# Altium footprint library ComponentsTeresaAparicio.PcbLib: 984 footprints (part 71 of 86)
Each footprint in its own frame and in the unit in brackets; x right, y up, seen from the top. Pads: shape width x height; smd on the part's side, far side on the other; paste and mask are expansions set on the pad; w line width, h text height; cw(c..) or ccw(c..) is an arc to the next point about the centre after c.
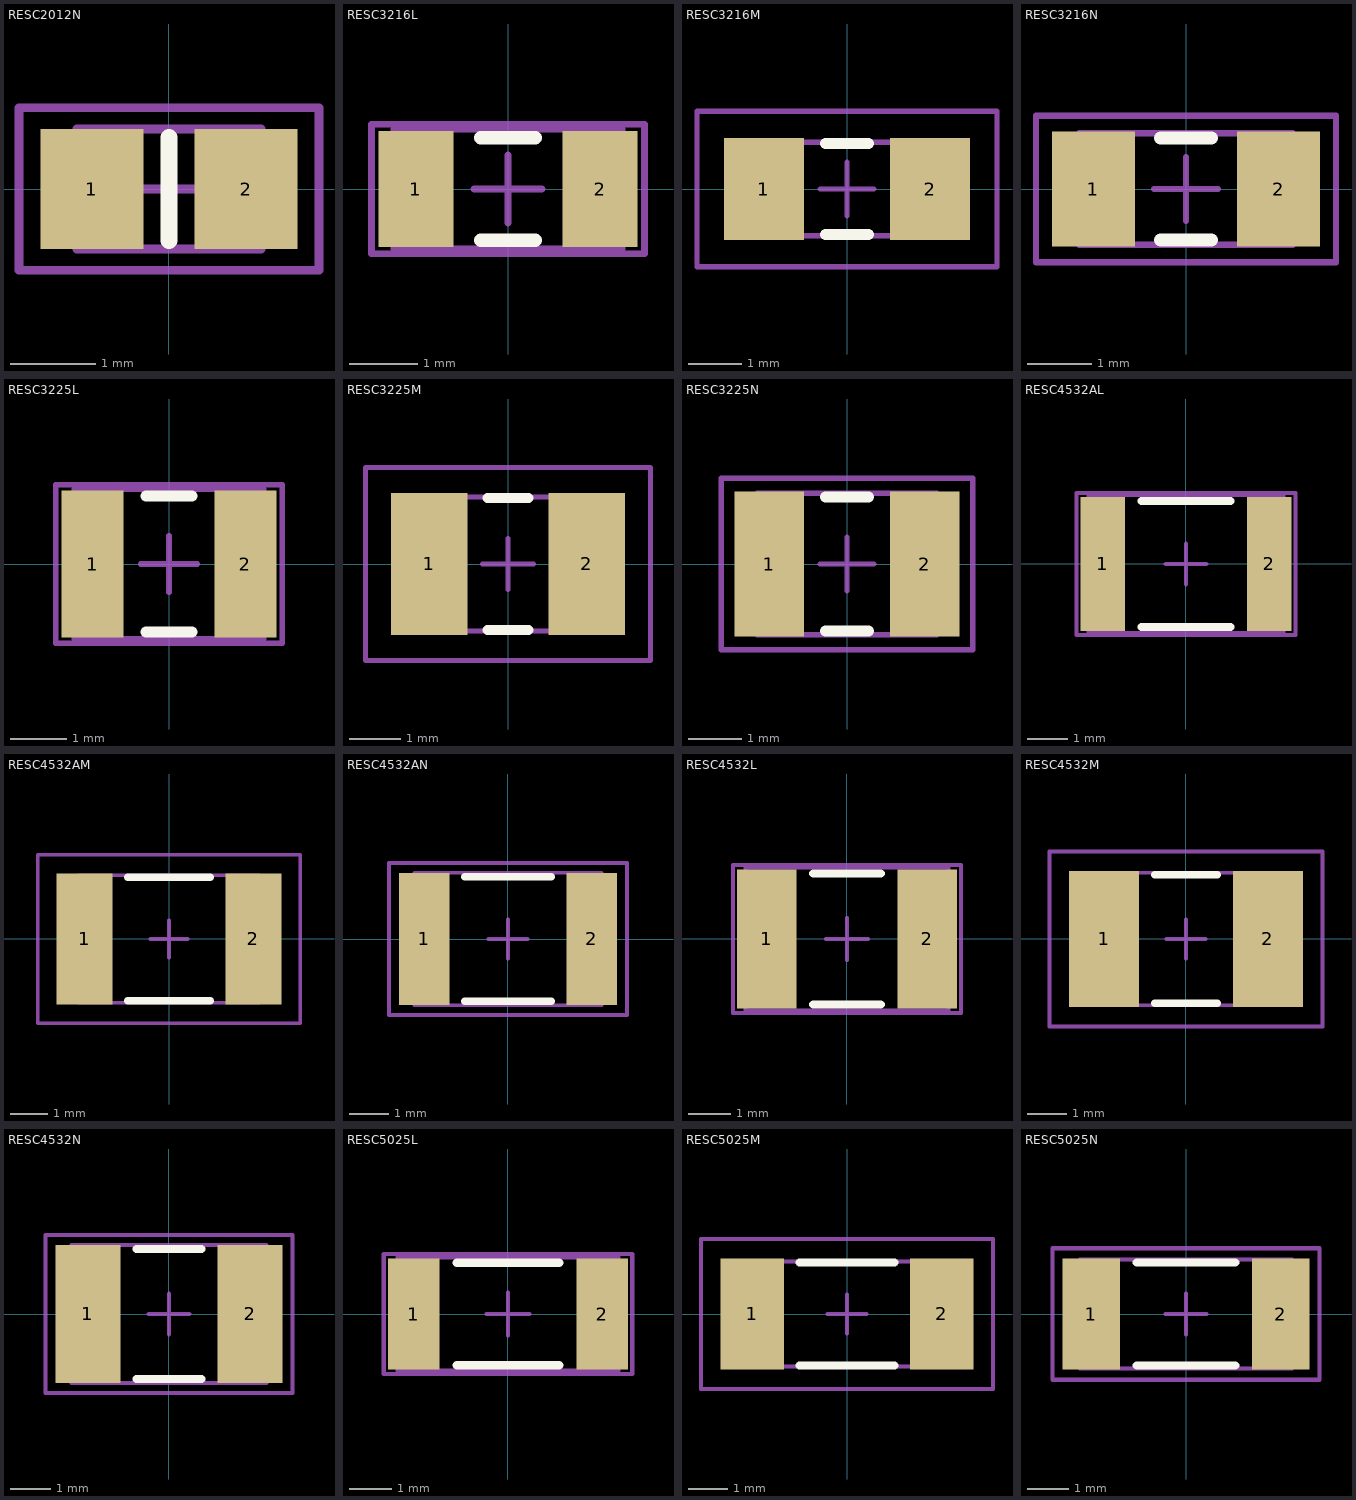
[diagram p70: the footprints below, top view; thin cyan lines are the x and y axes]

## RESC2012N [mm] "Chip Resistor, Body 2.0x1.3mm, IPC Medium Density"
height 0.65
pads (2):
  rect 1.2x1.4 smd: 1(-0.9,0) 2(0.9,0)
Top Overlay:
  lines w0.2: 0,-0.6 0,0.6
Mechanical 13:
  lines w0.1: -1.075,-0.7 1.075,-0.7 1.075,0.7 -1.075,0.7 -1.075,-0.7
Mechanical 15:
  lines w0.1: -0.5,0 0.5,0 ; 0,-0.5 0,0.5 ; -1.75,-0.95 1.75,-0.95 1.75,0.95 -1.75,0.95 -1.75,-0.95
3D body: height 0.65, standoff 0, extent -1.075,-0.7 1.075,0.7

## RESC3216L [mm] "Chip Resistor, Body 3.2x1.6mm, IPC High Density"
height 0.71
pads (2):
  rect 1.1x1.7 smd: 1(-1.35,0) 2(1.35,0)
Top Overlay:
  lines w0.2: -0.4,-0.75 0.4,-0.75 ; -0.4,0.75 0.4,0.75
Mechanical 13:
  lines w0.1: -1.675,-0.875 1.675,-0.875 1.675,0.875 -1.675,0.875 -1.675,-0.875
Mechanical 15:
  lines w0.1: -0.5,0 0.5,0 ; 0,-0.5 0,0.5 ; -2,-0.95 2,-0.95 2,0.95 -2,0.95 -2,-0.95
3D body: height 0.71, standoff 0, extent -1.675,-0.875 1.675,0.875

## RESC3216M [mm] "Chip Resistor, Body 3.2x1.6mm, IPC Low Density"
height 0.71
pads (2):
  rect 1.5x1.9 smd: 1(-1.55,0) 2(1.55,0)
Top Overlay:
  lines w0.2: -0.4,-0.85 0.4,-0.85 ; -0.4,0.85 0.4,0.85
Mechanical 13:
  lines w0.1: -1.675,-0.875 -1.675,0.875 1.675,0.875 1.675,-0.875 -1.675,-0.875
Mechanical 15:
  lines w0.1: -0.5,0 0.5,0 ; 0,-0.5 0,0.5 ; -2.8,-1.45 -2.8,1.45 2.8,1.45 2.8,-1.45 -2.8,-1.45
3D body: height 0.71, standoff 0, extent -1.675,-0.875 1.675,0.875

## RESC3216N [mm] "Chip Resistor, Body 3.2x1.6mm, IPC Medium Density"
height 0.71
pads (2):
  rect 1.3x1.8 smd: 1(-1.45,0) 2(1.45,0)
Top Overlay:
  lines w0.2: -0.4,-0.8 0.4,-0.8 ; -0.4,0.8 0.4,0.8
Mechanical 13:
  lines w0.1: -1.675,-0.875 -1.675,0.875 1.675,0.875 1.675,-0.875 -1.675,-0.875
Mechanical 15:
  lines w0.1: -0.5,0 0.5,0 ; 0,-0.5 0,0.5 ; -2.35,-1.15 -2.35,1.15 2.35,1.15 2.35,-1.15 -2.35,-1.15
3D body: height 0.71, standoff 0, extent -1.675,-0.875 1.675,0.875

## RESC3225L [mm] "Chip Resistor, Body 3.2x2.5mm, IPC High Density"
height 0.71
pads (2):
  rect 1.1x2.6 smd: 1(-1.35,0) 2(1.35,0)
Top Overlay:
  lines w0.2: -0.4,-1.2 0.4,-1.2 ; -0.4,1.2 0.4,1.2
Mechanical 13:
  lines w0.1: -1.675,-1.32 -1.675,1.32 1.675,1.32 1.675,-1.32 -1.675,-1.32
Mechanical 15:
  lines w0.1: -0.5,0 0.5,0 ; 0,-0.5 0,0.5 ; -2,-1.4 -2,1.4 2,1.4 2,-1.4 -2,-1.4
3D body: height 0.71, standoff 0, extent -1.675,-1.32 1.675,1.32

## RESC3225M [mm] "Chip Resistor, Body 3.2x2.5mm, IPC Low Density"
height 0.71
pads (2):
  rect 1.5x2.8 smd: 1(-1.55,0) 2(1.55,0)
Top Overlay:
  lines w0.2: -0.4,-1.3 0.4,-1.3 ; -0.4,1.3 0.4,1.3
Mechanical 13:
  lines w0.1: -1.675,-1.32 1.675,-1.32 1.675,1.32 -1.675,1.32 -1.675,-1.32
Mechanical 15:
  lines w0.1: -0.5,0 0.5,0 ; 0,-0.5 0,0.5 ; -2.8,-1.9 2.8,-1.9 2.8,1.9 -2.8,1.9 -2.8,-1.9
3D body: height 0.71, standoff 0, extent -1.675,-1.32 1.675,1.32

## RESC3225N [mm] "Chip Resistor, Body 3.2x2.5mm, IPC Medium Density"
height 0.71
pads (2):
  rect 1.3x2.7 smd: 1(-1.45,0) 2(1.45,0)
Top Overlay:
  lines w0.2: -0.4,-1.25 0.4,-1.25 ; -0.4,1.25 0.4,1.25
Mechanical 13:
  lines w0.1: -1.675,-1.32 1.675,-1.32 1.675,1.32 -1.675,1.32 -1.675,-1.32
Mechanical 15:
  lines w0.1: -0.5,0 0.5,0 ; 0,-0.5 0,0.5 ; -2.35,-1.6 2.35,-1.6 2.35,1.6 -2.35,1.6 -2.35,-1.6
3D body: height 0.71, standoff 0, extent -1.675,-1.32 1.675,1.32

## RESC4532AL [mm] "Chip Resistor, Body 4.5x3.2mm, IPC High Density"
height 0.7
pads (2):
  rect 1.1x3.3 smd: 1(-2.05,0) 2(2.05,0)
Top Overlay:
  lines w0.2: -1.1,-1.55 1.1,-1.55 ; -1.1,1.55 1.1,1.55
Mechanical 13:
  lines w0.1: -2.4,-1.7 2.4,-1.7 2.4,1.7 -2.4,1.7 -2.4,-1.7
Mechanical 15:
  lines w0.1: -0.5,0 0.5,0 ; 0,-0.5 0,0.5 ; -2.7,-1.75 2.7,-1.75 2.7,1.75 -2.7,1.75 -2.7,-1.75
3D body: height 0.7, standoff 0, extent -2.4,-1.7 2.4,1.7

## RESC4532AM [mm] "Chip Resistor, Body 4.5x3.2mm, IPC Low Density"
height 0.7
pads (2):
  rect 1.5x3.5 smd: 1(-2.25,0) 2(2.25,0)
Top Overlay:
  lines w0.2: -1.1,-1.65 1.1,-1.65 ; -1.1,1.65 1.1,1.65
Mechanical 13:
  lines w0.1: -2.4,-1.7 2.4,-1.7 2.4,1.7 -2.4,1.7 -2.4,-1.7
Mechanical 15:
  lines w0.1: -0.5,0 0.5,0 ; 0,-0.5 0,0.5 ; -3.5,-2.25 3.5,-2.25 3.5,2.25 -3.5,2.25 -3.5,-2.25
3D body: height 0.7, standoff 0, extent -2.4,-1.7 2.4,1.7

## RESC4532AN [mm] "Chip Resistor, Body 4.5x3.2mm, IPC Medium Density"
height 0.7
pads (2):
  rect 1.3x3.4 smd: 1(-2.15,0) 2(2.15,0)
Top Overlay:
  lines w0.2: -1.1,-1.6 1.1,-1.6 ; -1.1,1.6 1.1,1.6
Mechanical 13:
  lines w0.1: -2.4,-1.7 2.4,-1.7 2.4,1.7 -2.4,1.7 -2.4,-1.7
Mechanical 15:
  lines w0.1: -0.5,0 0.5,0 ; 0,-0.5 0,0.5 ; -3.05,-1.95 3.05,-1.95 3.05,1.95 -3.05,1.95 -3.05,-1.95
3D body: height 0.7, standoff 0, extent -2.4,-1.7 2.4,1.7

## RESC4532L [mm] "Chip Resistor, Body 4.5x3.2mm, IPC High Density"
height 0.71
pads (2):
  rect 1.4x3.3 smd: 1(-1.9,0) 2(1.9,0)
Top Overlay:
  lines w0.2: -0.8,-1.55 0.8,-1.55 ; -0.8,1.55 0.8,1.55
Mechanical 13:
  lines w0.1: -2.4,-1.7 2.4,-1.7 2.4,1.7 -2.4,1.7 -2.4,-1.7
Mechanical 15:
  lines w0.1: -0.5,0 0.5,0 ; 0,-0.5 0,0.5 ; -2.7,-1.75 2.7,-1.75 2.7,1.75 -2.7,1.75 -2.7,-1.75
3D body: height 0.71, standoff 0, extent -2.4,-1.7 2.4,1.7

## RESC4532M [mm] "Chip Resistor, Body 4.5x3.2mm, IPC Low Density"
height 0.71
pads (2):
  rect 1.8x3.5 smd: 1(-2.1,0) 2(2.1,0)
Top Overlay:
  lines w0.2: -0.8,-1.65 0.8,-1.65 ; -0.8,1.65 0.8,1.65
Mechanical 13:
  lines w0.1: -2.4,-1.7 2.4,-1.7 2.4,1.7 -2.4,1.7 -2.4,-1.7
Mechanical 15:
  lines w0.1: -0.5,0 0.5,0 ; 0,-0.5 0,0.5 ; -3.5,-2.25 3.5,-2.25 3.5,2.25 -3.5,2.25 -3.5,-2.25
3D body: height 0.71, standoff 0, extent -2.4,-1.7 2.4,1.7

## RESC4532N [mm] "Chip Resistor, Body 4.5x3.2mm, IPC Medium Density"
height 0.71
pads (2):
  rect 1.6x3.4 smd: 1(-2,0) 2(2,0)
Top Overlay:
  lines w0.2: -0.8,-1.6 0.8,-1.6 ; -0.8,1.6 0.8,1.6
Mechanical 13:
  lines w0.1: -2.4,-1.7 -2.4,1.7 2.4,1.7 2.4,-1.7 -2.4,-1.7
Mechanical 15:
  lines w0.1: -0.5,0 0.5,0 ; 0,-0.5 0,0.5 ; -3.05,-1.95 -3.05,1.95 3.05,1.95 3.05,-1.95 -3.05,-1.95
3D body: height 0.71, standoff 0, extent -2.4,-1.7 2.4,1.7

## RESC5025L [mm] "Chip Resistor, Body 5.0x2.5mm, IPC High Density"
height 0.71
pads (2):
  rect 1.2x2.6 smd: 1(-2.2,0) 2(2.2,0)
Top Overlay:
  lines w0.2: -1.2,-1.2 1.2,-1.2 ; -1.2,1.2 1.2,1.2
Mechanical 13:
  lines w0.1: -2.575,-1.325 2.575,-1.325 2.575,1.325 -2.575,1.325 -2.575,-1.325
Mechanical 15:
  lines w0.1: -0.5,0 0.5,0 ; 0,-0.5 0,0.5 ; -2.9,-1.4 2.9,-1.4 2.9,1.4 -2.9,1.4 -2.9,-1.4
3D body: height 0.71, standoff 0, extent -2.575,-1.325 2.575,1.325

## RESC5025M [mm] "Chip Resistor, Body 5.0x2.5mm, IPC Low Density"
height 0.71
pads (2):
  rect 1.6x2.8 smd: 1(-2.4,0) 2(2.4,0)
Top Overlay:
  lines w0.2: -1.2,-1.3 1.2,-1.3 ; -1.2,1.3 1.2,1.3
Mechanical 13:
  lines w0.1: -2.575,-1.325 2.575,-1.325 2.575,1.325 -2.575,1.325 -2.575,-1.325
Mechanical 15:
  lines w0.1: -0.5,0 0.5,0 ; 0,-0.5 0,0.5 ; -3.7,-1.9 3.7,-1.9 3.7,1.9 -3.7,1.9 -3.7,-1.9
3D body: height 0.71, standoff 0, extent -2.575,-1.325 2.575,1.325

## RESC5025N [mm] "Chip Resistor, Body 5.0x2.5mm, IPC Medium Density"
height 0.71
pads (2):
  rect 1.4x2.7 smd: 1(-2.3,0) 2(2.3,0)
Top Overlay:
  lines w0.2: -1.2,-1.25 1.2,-1.25 ; -1.2,1.25 1.2,1.25
Mechanical 13:
  lines w0.1: -2.575,-1.325 2.575,-1.325 2.575,1.325 -2.575,1.325 -2.575,-1.325
Mechanical 15:
  lines w0.1: -0.5,0 0.5,0 ; 0,-0.5 0,0.5 ; -3.25,-1.6 3.25,-1.6 3.25,1.6 -3.25,1.6 -3.25,-1.6
3D body: height 0.71, standoff 0, extent -2.575,-1.325 2.575,1.325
